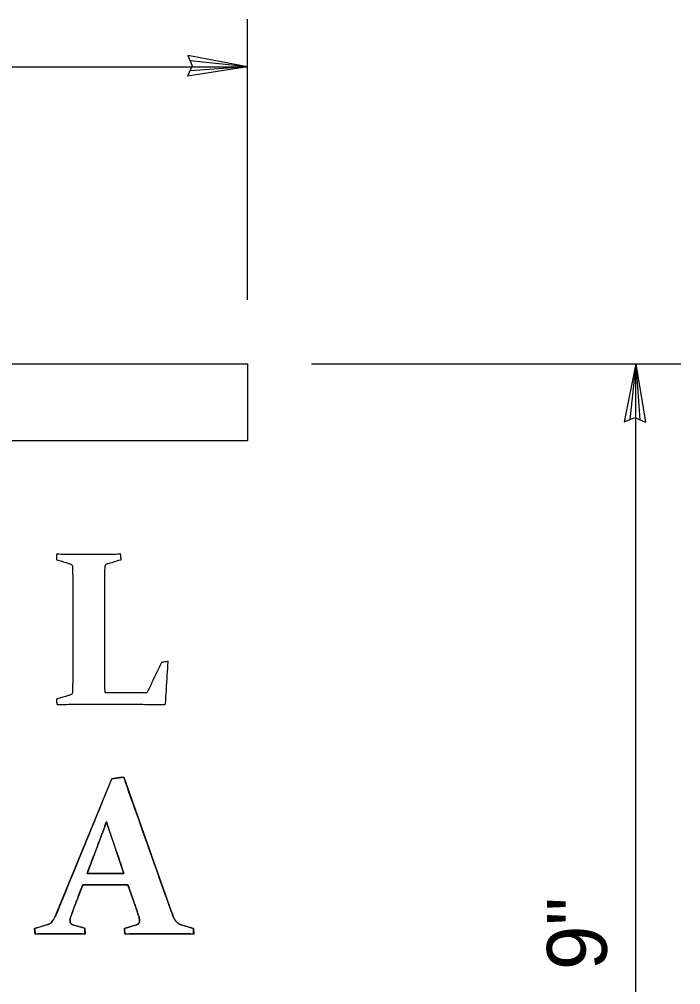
# Model space of a CAD drawing. Extents: x 60714 to 61343, y 7599 to 7998.
# Drawn here: x 60842.53 to 60873.47, y 7945.02 to 7990.16 of the extents above; entities that cross this region are included whole.
import ezdxf

# ---------------------------------------------------------------- set-up
doc = ezdxf.new("R2010")
doc.units = 0
for name, color, linetype in [('2', 7, 'Continuous'), ('21', 7, 'Continuous'), ('Default', 7, 'Continuous'), ('SignPanel', 7, 'Continuous')]:
    doc.layers.add(name, color=color, linetype=linetype)

# ---------------------------------------------------------------- blocks, each defined once
blk = doc.blocks.new('block 6')
at = {"layer": 'Default'}
blk.add_open_spline([(836.58, -467.12), (836.58, -467.12), (836.58, -501.78), (836.58, -501.78), (836.58, -504.99), (836.61, -508.17), (836.67, -511.33), (836.67, -511.33), (853.81, -511.33), (853.81, -511.33), (853.81, -511.33), (859.81, -498.88), (859.81, -498.88), (859.81, -498.88), (862.48, -498.49), (862.48, -498.49), (862.48, -498.49), (861.39, -515.8), (861.39, -515.8), (861.39, -515.8), (861.08, -516.1), (861.08, -516.1), (853.86, -516.02), (846.81, -515.97), (839.91, -515.97), (839.91, -515.97), (829.05, -515.97), (829.05, -515.97), (824.7, -515.97), (820.66, -516.02), (816.95, -516.1), (816.95, -516.1), (816.74, -513.91), (816.74, -513.91), (816.74, -513.91), (822.17, -512.29), (822.17, -512.29), (822.9, -512.09), (823.29, -511.64), (823.35, -510.93), (823.38, -509.77), (823.4, -508.46), (823.42, -507.01), (823.43, -505.57), (823.44, -503.97), (823.44, -502.21), (823.44, -502.21), (823.44, -467.29), (823.44, -467.29), (823.44, -465.83), (823.43, -464.5), (823.42, -463.3), (823.4, -462.11), (823.38, -461.01), (823.35, -460.02), (823.32, -459.26), (822.97, -458.78), (822.3, -458.57), (822.3, -458.57), (816.87, -456.86), (816.87, -456.86), (816.87, -456.86), (816.74, -454.63), (816.74, -454.63), (820.5, -454.75), (824.86, -454.8), (829.79, -454.8), (834.88, -454.8), (839.29, -454.75), (843.03, -454.63), (843.03, -454.63), (843.25, -456.86), (843.25, -456.86), (843.25, -456.86), (837.81, -458.48), (837.81, -458.48), (837.11, -458.66), (836.73, -459.1), (836.67, -459.8), (836.64, -460.85), (836.62, -462.35), (836.6, -464.29), (836.59, -466.23), (836.58, -467.17), (836.58, -467.12)], degree=3, dxfattribs=at)
blk.add_open_spline([(836.58, -467.12), (836.58, -467.12), (836.58, -501.78), (836.58, -501.78), (836.58, -504.99), (836.61, -508.17), (836.67, -511.33), (836.67, -511.33), (853.81, -511.33), (853.81, -511.33), (853.81, -511.33), (859.81, -498.88), (859.81, -498.88), (859.81, -498.88), (862.48, -498.49), (862.48, -498.49), (862.48, -498.49), (861.39, -515.8), (861.39, -515.8), (861.39, -515.8), (861.08, -516.1), (861.08, -516.1), (853.86, -516.02), (846.81, -515.97), (839.91, -515.97), (839.91, -515.97), (829.05, -515.97), (829.05, -515.97), (824.7, -515.97), (820.66, -516.02), (816.95, -516.1), (816.95, -516.1), (816.74, -513.91), (816.74, -513.91), (816.74, -513.91), (822.17, -512.29), (822.17, -512.29), (822.9, -512.09), (823.29, -511.64), (823.35, -510.93), (823.38, -509.77), (823.4, -508.46), (823.42, -507.01), (823.43, -505.57), (823.44, -503.97), (823.44, -502.21), (823.44, -502.21), (823.44, -467.29), (823.44, -467.29), (823.44, -465.83), (823.43, -464.5), (823.42, -463.3), (823.4, -462.11), (823.38, -461.01), (823.35, -460.02), (823.32, -459.26), (822.97, -458.78), (822.3, -458.57), (822.3, -458.57), (816.87, -456.86), (816.87, -456.86), (816.87, -456.86), (816.74, -454.63), (816.74, -454.63), (820.5, -454.75), (824.86, -454.8), (829.79, -454.8), (834.88, -454.8), (839.29, -454.75), (843.03, -454.63), (843.03, -454.63), (843.25, -456.86), (843.25, -456.86), (843.25, -456.86), (837.81, -458.48), (837.81, -458.48), (837.11, -458.66), (836.73, -459.1), (836.67, -459.8), (836.64, -460.85), (836.62, -462.35), (836.6, -464.29), (836.59, -466.23), (836.58, -467.17), (836.58, -467.12)], degree=3, dxfattribs=at)
blk = doc.blocks.new('block 9')
at = {"layer": 'Default'}
for points in [[(816.99, -601.1), (839.42, -546.47), (844.29, -545.75), (863.7, -600.51)], [(835.5, -568.8), (829.34, -585.11), (844.37, -585.11), (838.84, -568.85)], [(848.97, -598.26), (846, -589.79), (827.53, -589.79), (824.34, -598.21)], [(808.08, -609.92), (807.86, -607.67), (812.67, -606.23)], [(824.02, -606.32), (828.35, -607.58), (828.48, -609.92)], [(844.78, -609.92), (844.56, -607.67), (849.01, -606.36)], [(868.38, -606.36), (872.79, -607.67), (872.93, -609.92)]]:
    blk.add_lwpolyline(points, dxfattribs=at)
for points, degree in [([(827.53, -589.79), (827.53, -589.79), (824.34, -598.21), (824.34, -598.21), (823.71, -599.86), (823.22, -601.19), (822.87, -602.2), (822.53, -603.2), (822.35, -603.98), (822.35, -604.52), (822.35, -605.02), (822.49, -605.42), (822.76, -605.69), (823.03, -605.96), (823.45, -606.17), (824.02, -606.32), (824.02, -606.32), (828.35, -607.58), (828.35, -607.58), (828.35, -607.58), (828.48, -609.92), (828.48, -609.92), (824.13, -609.83), (820.58, -609.79), (817.85, -609.79), (815, -609.79), (811.74, -609.83), (808.08, -609.92), (808.08, -609.92), (807.86, -607.67), (807.86, -607.67), (807.86, -607.67), (812.67, -606.23), (812.67, -606.23), (813.81, -605.9), (814.66, -605.35), (815.19, -604.58), (815.74, -603.82), (816.34, -602.66), (816.99, -601.1), (816.99, -601.1), (839.42, -546.47), (839.42, -546.47), (839.42, -546.47), (844.29, -545.75), (844.29, -545.75), (844.29, -545.75), (863.7, -600.51), (863.7, -600.51), (864.45, -602.61), (865.13, -604.03), (865.75, -604.76), (866.36, -605.5), (867.24, -606.03), (868.38, -606.36), (868.38, -606.36), (872.79, -607.67), (872.79, -607.67), (872.79, -607.67), (872.93, -609.92), (872.93, -609.92), (868.87, -609.83), (864.79, -609.79), (860.68, -609.79), (855.25, -609.79), (849.94, -609.83), (844.78, -609.92), (844.78, -609.92), (844.56, -607.67), (844.56, -607.67), (844.56, -607.67), (849.01, -606.36), (849.01, -606.36), (849.62, -606.18), (850.05, -605.96), (850.32, -605.69), (850.59, -605.42), (850.73, -605.02), (850.73, -604.47), (850.73, -603.87), (850.58, -603.08), (850.28, -602.11), (849.98, -601.13), (849.54, -599.85), (848.97, -598.26), (848.97, -598.26), (846, -589.79), (846, -589.79), (846, -589.79), (827.53, -589.79), (827.53, -589.79)], 3), ([(837.26, -563.94), (836.72, -565.5), (836.14, -567.12), (835.5, -568.8), (835.5, -568.8), (829.34, -585.11), (829.34, -585.11), (829.34, -585.11), (844.37, -585.11), (844.37, -585.11), (844.37, -585.11), (838.84, -568.85), (838.84, -568.85), (838.27, -567.14), (837.74, -565.5), (837.26, -563.94)], 3), ([(837.26, -563.94), (836.72, -565.5), (836.14, -567.12), (835.5, -568.8)], 2), ([(838.84, -568.85), (838.27, -567.14), (837.74, -565.5), (837.26, -563.94)], 2), ([(824.34, -598.21), (823.71, -599.86), (823.22, -601.19), (822.87, -602.2), (822.53, -603.2), (822.35, -603.98), (822.35, -604.52), (822.35, -605.02), (822.49, -605.42), (822.76, -605.69), (823.03, -605.96), (823.45, -606.17), (824.02, -606.32)], 3), ([(849.01, -606.36), (849.62, -606.18), (850.05, -605.96), (850.32, -605.69), (850.59, -605.42), (850.73, -605.02), (850.73, -604.47), (850.73, -603.87), (850.58, -603.08), (850.28, -602.11), (849.98, -601.13), (849.54, -599.85), (848.97, -598.26)], 3), ([(812.67, -606.23), (813.81, -605.9), (814.66, -605.35), (815.19, -604.58), (815.74, -603.82), (816.34, -602.66), (816.99, -601.1)], 3), ([(863.7, -600.51), (864.45, -602.61), (865.13, -604.03), (865.75, -604.76), (866.36, -605.5), (867.24, -606.03), (868.38, -606.36)], 3), ([(828.48, -609.92), (824.13, -609.83), (820.58, -609.79), (817.85, -609.79), (815, -609.79), (811.74, -609.83), (808.08, -609.92)], 3), ([(872.93, -609.92), (868.87, -609.83), (864.79, -609.79), (860.68, -609.79), (855.25, -609.79), (849.94, -609.83), (844.78, -609.92)], 3)]:
    blk.add_open_spline(points, degree=degree, dxfattribs=at)

msp = doc.modelspace()

# ---------------------------------------------------------------- linework, layer by layer
at = {"layer": '2'}
for p, q in [((60853.206, 7977.045), (60853.206, 7990.16)), ((60787.934, 7987.941), (60853.206, 7987.941)), ((60856.206, 7974.045), (60873.475, 7974.045)), ((60871.375, 7921.118), (60871.375, 7974.045))]:
    msp.add_line(p, q, dxfattribs=at)
at = {"layer": '21'}
for p, q in [((60853.206, 7987.941), (60850.417, 7988.467)), ((60850.417, 7988.467), (60850.623, 7987.984)), ((60853.206, 7987.941), (60850.525, 7988.213)), ((60850.623, 7987.984), (60850.4, 7987.507)), ((60853.206, 7987.941), (60850.4, 7987.507)), ((60853.206, 7987.941), (60850.519, 7987.758)), ((60871.375, 7974.045), (60870.834, 7971.337)), ((60871.375, 7974.045), (60871.095, 7971.441)), ((60871.375, 7974.045), (60871.82, 7971.319)), ((60871.375, 7974.045), (60871.563, 7971.435)), ((60870.834, 7971.337), (60871.331, 7971.536)), ((60871.331, 7971.536), (60871.82, 7971.319))]:
    msp.add_line(p, q, dxfattribs=at)
at = {"layer": 'SignPanel'}
msp.add_lwpolyline([(60787.934, 7974.045), (60853.206, 7974.045), (60853.206, 7970.441), (60787.934, 7970.441), (60787.934, 7974.045)], dxfattribs=at)

# ---------------------------------------------------------------- block references
at = {"layer": 'SignPanel', "xscale": 0.11437403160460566, "yscale": 0.11437403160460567, "rotation": 2.962189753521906e-08}
for name in ['block 6', 'block 9']:
    msp.add_blockref(name, (60750.847, 8017.145), dxfattribs=at)

# ---------------------------------------------------------------- texts
at = {"layer": '2'}
msp.add_text('9"', height=2.8, rotation=90, dxfattribs=at).set_placement((60870.018, 7945.699))

doc.saveas('drawing.dxf')
